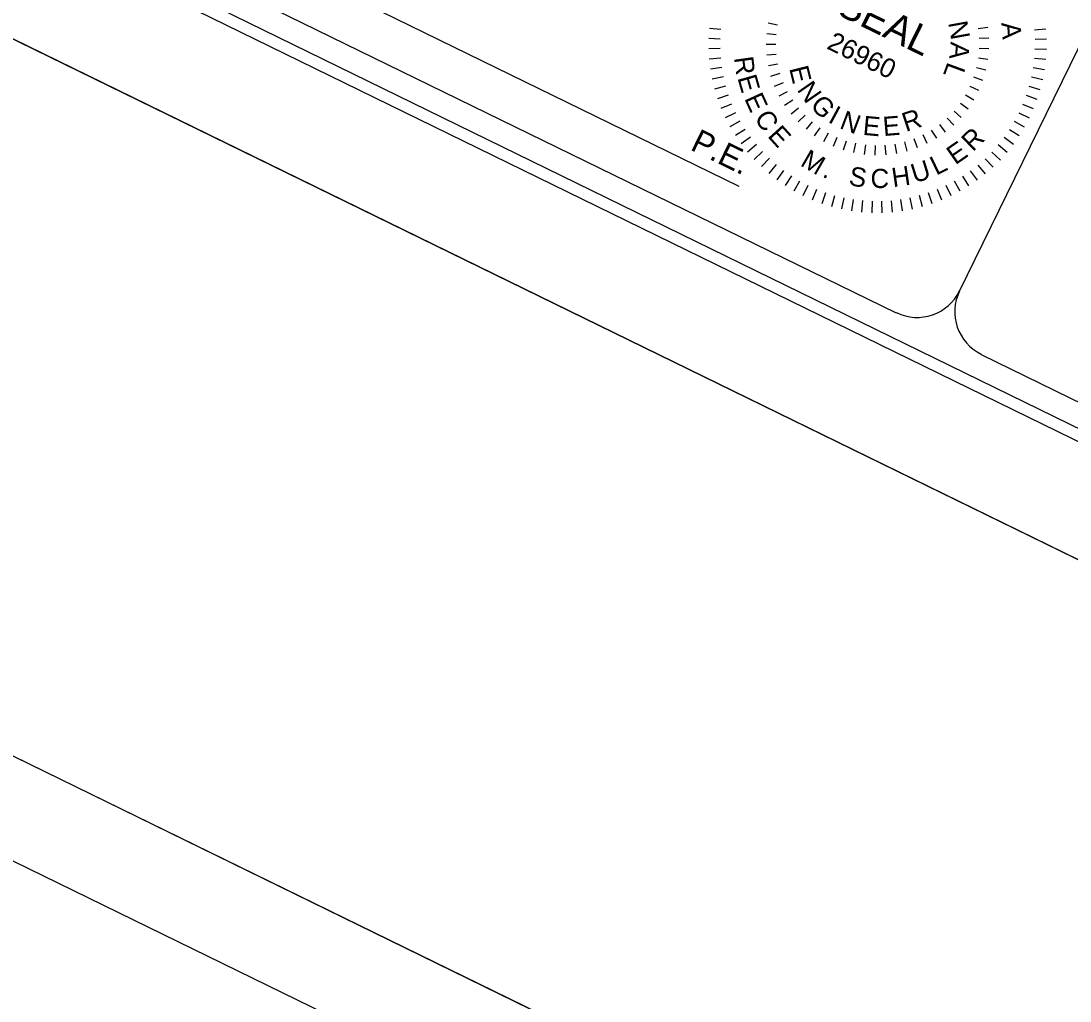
# Model space of a CAD drawing. Extents: x 1517888 to 1526099, y 633375 to 640181.
# Drawn here: x 1520197.1 to 1520641.2, y 636669.4 to 637084.4 of the extents above; entities that cross this region are included whole.
import ezdxf

# ---------------------------------------------------------------- set-up
doc = ezdxf.new("R2010")
doc.units = 0
for name, color, linetype in [('Default', 7, 'Continuous'), ('Sheet Cutting Line CELL', 7, 'Continuous'), ('Sheet Plot Border Inside CELL', 7, 'Continuous'), ('Sheet Plot Border Outside CELL', 7, 'Continuous'), ('Sheet Title CELL', 7, 'Continuous')]:
    doc.layers.add(name, color=color, linetype=linetype)

msp = doc.modelspace()

# ---------------------------------------------------------------- linework, layer by layer
at = {"layer": 'Default'}
for p, q in [((1520513.42, 637083.62), (1520517.41, 637082.85)), ((1520606.35, 637081.69), (1520602.33, 637081.08)), ((1520488.5, 637081.38), (1520493.36, 637080.93)), ((1520512.78, 637079.11), (1520516.83, 637078.73)), ((1520630.98, 637081), (1520626.12, 637080.57)), ((1520488.22, 637072.75), (1520493.09, 637072.88)), ((1520488.23, 637077.07), (1520493.1, 637076.91)), ((1520512.58, 637074.56), (1520516.64, 637074.58)), ((1520606.8, 637077.16), (1520602.75, 637076.94)), ((1520631.23, 637076.68), (1520626.35, 637076.55)), ((1520488.47, 637068.43), (1520493.32, 637068.87)), ((1520512.81, 637070.02), (1520516.85, 637070.41)), ((1520606.39, 637068.06), (1520602.37, 637068.64)), ((1520606.82, 637072.6), (1520602.76, 637072.78)), ((1520630.95, 637068.05), (1520626.09, 637068.5)), ((1520631.21, 637072.36), (1520626.34, 637072.53)), ((1520488.98, 637064.14), (1520493.8, 637064.86)), ((1520513.48, 637065.5), (1520517.47, 637066.3)), ((1520605.54, 637063.59), (1520601.59, 637064.55)), ((1520630.42, 637063.77), (1520625.59, 637064.52)), ((1520489.74, 637059.9), (1520494.51, 637060.9)), ((1520514.59, 637061.09), (1520518.48, 637062.26)), ((1520604.25, 637059.22), (1520600.41, 637060.56)), ((1520629.62, 637059.51), (1520624.86, 637060.56)), ((1520490.77, 637055.69), (1520495.47, 637056.99)), ((1520516.11, 637056.8), (1520519.88, 637058.34)), ((1520602.55, 637054.99), (1520598.86, 637056.69)), ((1520628.58, 637055.32), (1520623.89, 637056.65)), ((1520492.04, 637051.57), (1520496.65, 637053.14)), ((1520518.05, 637052.67), (1520521.64, 637054.57)), ((1520520.37, 637048.75), (1520523.77, 637050.99)), ((1520600.44, 637050.95), (1520596.93, 637053)), ((1520627.28, 637051.2), (1520622.68, 637052.81)), ((1520493.56, 637047.52), (1520498.07, 637049.37)), ((1520523.07, 637045.07), (1520526.23, 637047.63)), ((1520595.12, 637043.57), (1520592.07, 637046.25)), ((1520594.74, 637049.63), (1520598.05, 637047.26)), ((1520625.74, 637047.17), (1520621.24, 637049.05)), ((1520495.33, 637043.57), (1520499.71, 637045.7)), ((1520497.32, 637039.75), (1520501.57, 637042.13)), ((1520526.1, 637041.67), (1520529, 637044.52)), ((1520532.03, 637041.71), (1520529.42, 637038.6)), ((1520591.94, 637040.3), (1520589.17, 637043.26)), ((1520621.93, 637039.41), (1520617.69, 637041.81)), ((1520623.95, 637043.23), (1520619.57, 637045.38)), ((1520499.54, 637036.04), (1520503.65, 637038.67)), ((1520533.07, 637035.83), (1520535.37, 637039.18)), ((1520584.74, 637034.76), (1520582.58, 637038.19)), ((1520588.47, 637037.36), (1520586, 637040.58)), ((1520619.69, 637035.72), (1520615.6, 637038.37)), ((1520501.99, 637032.48), (1520505.93, 637035.36)), ((1520536.95, 637033.43), (1520538.91, 637037)), ((1520541.04, 637031.43), (1520542.65, 637035.16)), ((1520545.3, 637029.83), (1520546.55, 637033.7)), ((1520572.27, 637029.27), (1520571.18, 637033.19)), ((1520576.59, 637030.7), (1520575.14, 637034.48)), ((1520580.76, 637032.52), (1520578.94, 637036.16)), ((1520617.23, 637032.17), (1520613.31, 637035.07)), ((1520504.65, 637029.07), (1520508.4, 637032.18)), ((1520507.5, 637025.82), (1520511.07, 637029.16)), ((1520549.7, 637028.65), (1520550.57, 637032.63)), ((1520554.19, 637027.9), (1520554.67, 637031.94)), ((1520558.74, 637027.59), (1520558.83, 637031.65)), ((1520563.3, 637027.71), (1520562.99, 637031.76)), ((1520567.82, 637028.27), (1520567.12, 637032.27)), ((1520611.68, 637025.54), (1520608.13, 637028.9)), ((1520614.55, 637028.78), (1520610.81, 637031.9)), ((1520510.55, 637022.76), (1520513.9, 637026.31)), ((1520608.62, 637022.5), (1520605.28, 637026.06)), ((1520513.78, 637019.89), (1520516.91, 637023.63)), ((1520517.17, 637017.21), (1520520.07, 637021.13)), ((1520601.97, 637016.99), (1520599.08, 637020.92)), ((1520605.37, 637019.65), (1520602.26, 637023.4)), ((1520520.72, 637014.75), (1520523.38, 637018.84)), ((1520524.41, 637012.51), (1520526.82, 637016.75)), ((1520594.69, 637012.32), (1520592.31, 637016.57)), ((1520598.4, 637014.54), (1520595.77, 637018.65)), ((1520528.24, 637010.49), (1520530.38, 637014.87)), ((1520532.17, 637008.7), (1520534.05, 637013.2)), ((1520536.21, 637007.16), (1520537.81, 637011.76)), ((1520582.87, 637007.04), (1520581.3, 637011.65)), ((1520586.92, 637008.56), (1520585.07, 637013.07)), ((1520590.87, 637010.32), (1520588.74, 637014.71)), ((1520540.33, 637005.86), (1520541.65, 637010.55)), ((1520544.52, 637004.82), (1520545.56, 637009.58)), ((1520548.77, 637004.02), (1520549.52, 637008.85)), ((1520553.06, 637003.49), (1520553.51, 637008.35)), ((1520557.37, 637003.23), (1520557.53, 637008.1)), ((1520561.69, 637003.21), (1520561.56, 637008.09)), ((1520566.01, 637003.46), (1520565.57, 637008.32)), ((1520570.3, 637003.97), (1520569.57, 637008.79)), ((1520574.54, 637004.74), (1520573.54, 637009.51)), ((1520578.75, 637005.76), (1520577.45, 637010.46))]:
    msp.add_line(p, q, dxfattribs=at)
at = {"layer": 'Sheet Cutting Line CELL'}
for p, q in [((1518399.92, 637954.19), (1521425.45, 636474.47)), ((1523118.12, 635342.8), (1520093.48, 636822.08))]:
    msp.add_line(p, q, dxfattribs=at)
at = {"layer": 'Sheet Plot Border Inside CELL'}
for points in [[(1517931.1, 638233.43), (1520925.19, 636769.09), (1521852.3, 638664.72), (1518858.21, 640129.06)], [(1519172.24, 634879.28), (1522165.43, 633415.37), (1523092.46, 635310.82), (1520099.27, 636774.73)]]:
    msp.add_lwpolyline(points, close=True, dxfattribs=at)
at = {"layer": 'Sheet Plot Border Outside CELL'}
for points in [[(1521880.11, 638701.1), (1518854.58, 640180.82), (1517888.03, 638204.54), (1520913.56, 636724.82)], [(1519131.31, 634854.77), (1522155.94, 633375.48), (1523118.12, 635342.8), (1520093.48, 636822.08)]]:
    msp.add_lwpolyline(points, close=True, dxfattribs=at)
at = {"layer": 'Sheet Title CELL'}
for p, q in [((1520594.36, 636969.99), (1520734.95, 637257.45)), ((1520246.75, 637138.78), (1520500.96, 637014.42))]:
    msp.add_line(p, q, dxfattribs=at)
for points in [[(1518227.99, 638093.91), (1520887.01, 636793.44)], [(1520208.69, 637136.35), (1520567.61, 636960.81)], [(1520603.54, 636943.23), (1520882.43, 636806.84)]]:
    msp.add_lwpolyline(points, dxfattribs=at)
for centre, start, end in [((1520576.45, 636978.88), 243.9377, 333.9377), ((1520612.38, 636961.3), 153.9377, 243.9377)]:
    msp.add_arc(centre, 20, start, end, dxfattribs=at)

# ---------------------------------------------------------------- texts
at = {"layer": 'Default'}
for s, height, rotation, p in [('SEAL', 12.189, 333.8847, (1520541.72, 637087.61)), ('N', 8.12, 280.3478, (1520589.57, 637083.69)), ('A', 8.12, 274.4018, (1520612.08, 637083.65)), ('26960', 8.119, 333.8847, (1520537.79, 637072.9)), ('A', 8.12, 265.0516, (1520590.64, 637075.76)), ('R', 8.12, 277.8197, (1520498.91, 637068.89)), ('E', 8.12, 283.9548, (1520522.24, 637064.37)), ('L', 8.12, 249.7554, (1520589.46, 637067.39)), ('E', 8.12, 285.8915, (1520500.34, 637060.38)), ('N', 8.12, 304.8099, (1520525.38, 637055.29)), ('E', 8.12, 294.5343, (1520503.17, 637051.62)), ('G', 8.12, 313.5761, (1520530.84, 637048.38)), ('C', 8.12, 303.2069, (1520507.29, 637043.39)), ('I', 8.12, 331.6709, (1520538.38, 637041.78)), ('N', 8.12, 339.3006, (1520543.21, 637039.12)), ('R', 8.12, 18.4496, (1520571.69, 637037.34)), ('E', 8.12, 354.6926, (1520553.24, 637036.22)), ('E', 8.12, 4.6785, (1520562.25, 637035.66)), ('E', 8.12, 312.1794, (1520512.84, 637035.57)), ('R', 8.12, 43.5571, (1520599.97, 637028.78)), ('E', 8.12, 34.8844, (1520592.61, 637023.25)), ('M', 8.12, 329.9747, (1520526.58, 637023.38)), ('U', 8.12, 17.2091, (1520575.34, 637015.67)), ('L', 8.12, 26.0918, (1520584.5, 637018.9)), ('S', 8.12, 350.5013, (1520547.19, 637014.94)), ('C', 8.12, 359.5039, (1520556.7, 637013.71)), ('H', 8.12, 8.3265, (1520566.28, 637014)), ('.', 8.12, 337.717, (1520535.98, 637018.49))]:
    msp.add_text(s, height=height, rotation=rotation, dxfattribs=at).set_placement(p)
at = {"layer": 'Sheet Title CELL'}
msp.add_text('P.E.', height=9.999, rotation=333.9377, dxfattribs=at).set_placement((1520479.99, 637030.04))

doc.saveas('drawing.dxf')
